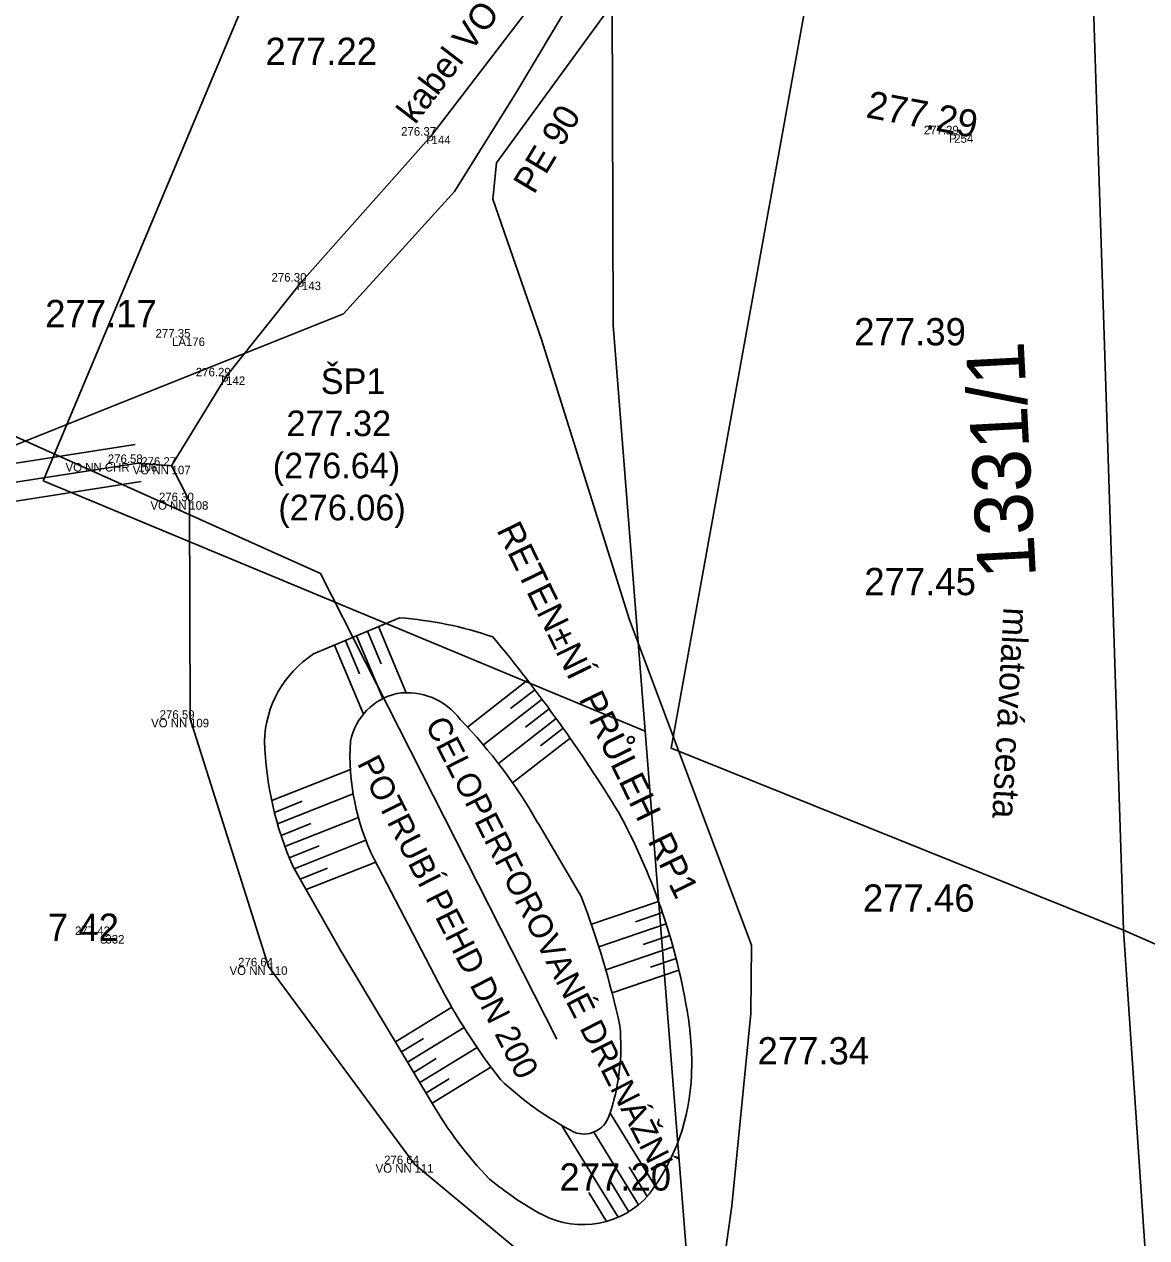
# Model space of a CAD drawing. Extents: x -601602 to -600882, y -1162594 to -1161950.
# Drawn here: x -601167.11 to -601150.66, y -1162070.19 to -1162052.4 of the extents above; entities that cross this region are included whole.
import ezdxf

# ---------------------------------------------------------------- set-up
doc = ezdxf.new("R2010")
doc.units = 0
for name, color, linetype in [('BODY', 7, 'Continuous'), ('BODY_CISLA', 7, 'Continuous'), ('BODY_KODY', 7, 'Continuous'), ('BODY_VYSKY_CELE', 7, 'Continuous'), ('G_TEXTY', 7, 'Continuous'), ('H_KOTY_VYSKOVE', 7, 'Continuous'), ('H_VYSKY_PREVZATE', 7, 'Continuous'), ('IS_CHRÁNIČKY', 7, 'Continuous'), ('IS_EON_NN', 7, 'Continuous'), ('IS_ODVODNENI_HDV', 7, 'Continuous'), ('IS_VO_AREAL', 7, 'Continuous'), ('IS_VODOVOD', 7, 'Continuous'), ('KN_Hranice parcel', 7, 'Continuous'), ('KN_Parcelní čísla', 7, 'Continuous'), ('KN_Vnitřní kresba', 7, 'Continuous')]:
    doc.layers.add(name, color=color, linetype=linetype)

# ---------------------------------------------------------------- blocks, each defined once
blk = doc.blocks.new('POINT_DISPLAY')
blk.add_line((0, 0), (0, 0))

msp = doc.modelspace()

# ---------------------------------------------------------------- linework, layer by layer
at = {"layer": 'IS_CHRÁNIČKY'}
for p, q in [((-601173.772, -1162059.848), (-601165.482, -1162058.558)), ((-601173.688, -1162060.392), (-601165.398, -1162059.102))]:
    msp.add_line(p, q, dxfattribs=at)
at = {"layer": 'IS_EON_NN'}
for points in [[(-601163.98, -1162016.16), (-601163.33, -1162016.88), (-601160.71, -1162020.48), (-601159.11, -1162022.87), (-601157.71, -1162024.95), (-601156.75, -1162026.36), (-601155.85, -1162028.35), (-601154.65, -1162035.5), (-601155.01, -1162041.12), (-601155.31, -1162044.77), (-601156.69, -1162049.18), (-601157.91, -1162051.3), (-601160.19, -1162054.43), (-601160.24, -1162054.96), (-601159.53, -1162057.02), (-601158.24, -1162061.13), (-601156.45, -1162065.9)], [(-601156.45, -1162065.9), (-601156.46, -1162066.9), (-601156.74, -1162069.72), (-601157.04, -1162071.88), (-601156.69, -1162072.3), (-601155.65, -1162072.6), (-601154.16, -1162073.09), (-601152, -1162074.34), (-601150.35, -1162074.97), (-601148.58, -1162075.26), (-601146.13, -1162075.74), (-601143.03, -1162076.23), (-601141.99, -1162076.23)]]:
    msp.add_lwpolyline(points, dxfattribs=at)
at = {"layer": 'IS_ODVODNENI_HDV'}
for p, q in [((-601162.77, -1162060.45), (-601172.63, -1162056.02)), ((-601159.303, -1162067.276), (-601162.77, -1162060.45)), ((-601162.87, -1162061.63), (-601161.61, -1162061.1)), ((-601161.917, -1162061.229), (-601161.51, -1162062.198)), ((-601162.401, -1162061.433), (-601162.196, -1162061.919)), ((-601162.24, -1162061.365), (-601161.853, -1162062.285)), ((-601162.078, -1162061.297), (-601161.878, -1162061.772)), ((-601162.562, -1162061.501), (-601162.137, -1162062.511)), ((-601159.732, -1162062.015), (-601160.614, -1162062.702)), ((-601159.521, -1162062.294), (-601160.381, -1162062.964)), ((-601159.626, -1162062.154), (-601159.982, -1162062.431)), ((-601159.417, -1162062.434), (-601159.762, -1162062.703)), ((-601159.314, -1162062.576), (-601160.161, -1162063.236)), ((-601159.212, -1162062.719), (-601159.543, -1162062.976)), ((-601159.111, -1162062.862), (-601159.953, -1162063.519)), ((-601163.483, -1162063.779), (-601162.329, -1162063.322)), ((-601163.398, -1162064.122), (-601162.288, -1162063.682)), ((-601163.443, -1162063.952), (-601163.035, -1162063.79)), ((-601163.289, -1162064.455), (-601162.212, -1162064.028)), ((-601163.346, -1162064.289), (-601162.911, -1162064.117)), ((-601158.94, -1162065.2), (-601159.58, -1162064.11)), ((-601163.226, -1162064.619), (-601162.787, -1162064.444)), ((-601163.154, -1162064.779), (-601162.102, -1162064.362)), ((-601163.17, -1162064.75), (-601162.47, -1162065.98)), ((-601163.067, -1162064.932), (-601162.663, -1162064.772)), ((-601162.979, -1162065.085), (-601161.959, -1162064.681)), ((-601161.98, -1162064.64), (-601161.04, -1162066.45)), ((-601157.813, -1162065.257), (-601158.798, -1162065.593)), ((-601157.755, -1162065.421), (-601158.149, -1162065.556)), ((-601157.701, -1162065.588), (-601158.688, -1162065.925)), ((-601157.649, -1162065.756), (-601158.04, -1162065.889)), ((-601162.47, -1162065.98), (-601161.14, -1162068.2)), ((-601157.601, -1162065.924), (-601158.587, -1162066.26)), ((-601157.556, -1162066.093), (-601157.931, -1162066.221)), ((-601157.514, -1162066.264), (-601158.495, -1162066.599)), ((-601161.67, -1162067.315), (-601160.845, -1162066.807)), ((-601161.491, -1162067.615), (-601160.664, -1162067.106)), ((-601161.58, -1162067.465), (-601161.259, -1162067.267)), ((-601161.311, -1162067.915), (-601160.472, -1162067.4)), ((-601161.401, -1162067.765), (-601161.071, -1162067.562)), ((-601161.131, -1162068.215), (-601160.27, -1162067.686)), ((-601161.221, -1162068.065), (-601160.883, -1162067.857)), ((-601157.865, -1162069.431), (-601158.523, -1162068.36)), ((-601158.406, -1162069.888), (-601159.234, -1162068.539)), ((-601158.108, -1162069.705), (-601158.761, -1162068.639)), ((-601157.978, -1162069.582), (-601158.244, -1162069.149)), ((-601158.251, -1162069.807), (-601158.539, -1162069.337)), ((-601158.574, -1162069.949), (-601158.834, -1162069.525))]:
    msp.add_line(p, q, dxfattribs=at)
for centre, radius, start, end in [((-601162.012, -1162066.56), 5.475, 71.1121, 85.7859), ((-601177.14, -1162075.423), 21.973, 31.4764, 39.7253), ((-601162.002, -1162062.961), 1.589, 123.1219, 178.1626), ((-601161.439, -1162063.095), 0.91, 103.4054, 168.2552), ((-601161.497, -1162063.164), 0.966, 36.4513, 99.0987), ((-601166.099, -1162067.811), 7.496, 29.5891, 44.1507), ((-601158.598, -1162062.738), 4.995, 181.9681, 203.7481), ((-601158.86, -1162063.108), 3.476, 176.7278, 206.1467), ((-601166.493, -1162068.374), 9.223, 9.6345, 28.6618), ((-601171.324, -1162069.912), 13.25, 12.3422, 20.8324), ((-601152.81, -1162062.178), 9.273, 207.4357, 217.8714), ((-601161.756, -1162067.632), 4.429, 357.8246, 10.4306), ((-601161.512, -1162067.378), 3.146, 340.8482, 5.4323), ((-601160.438, -1162067.684), 3.11, 323.127, 357.856), ((-601156.841, -1162064.399), 4.782, 226.5413, 242.4838), ((-601156.188, -1162065.359), 5.709, 209.8375, 224.0644), ((-601158.907, -1162068.278), 0.39, 248.3957, 340.1531), ((-601157.239, -1162065.642), 4.786, 230.3975, 241.5382), ((-601158.923, -1162068.714), 1.283, 242.2848, 319.3509)]:
    msp.add_arc(centre, radius, start, end, dxfattribs=at)
at = {"layer": 'IS_VO_AREAL'}
for points in [[(-601164.95, -1162058.87), (-601164.15, -1162057.56), (-601163.04, -1162056.17), (-601161.14, -1162054.03), (-601158.99, -1162051.22), (-601157.56, -1162048.96), (-601156.33, -1162045.65), (-601156.093, -1162044.563), (-601155.26, -1162040.45), (-601155.6, -1162034.28), (-601155.52, -1162031.87), (-601155.34, -1162029.97), (-601155.68, -1162028.1), (-601156.76, -1162025.67), (-601158.14, -1162023.37), (-601162.335, -1162016.886), (-601163.35, -1162015.61), (-601164.14, -1162013.65), (-601164.03, -1162012.35), (-601163.65, -1162011.09), (-601163.81, -1162009.97)], [(-601180.2, -1162059.82), (-601173.73, -1162060.12), (-601165.44, -1162058.83), (-601164.95, -1162058.87), (-601164.69, -1162059.39), (-601164.68, -1162062.58), (-601163.53, -1162066.21), (-601161.39, -1162069.11), (-601159.39, -1162070.77), (-601156.11, -1162072.49), (-601153.69, -1162072.64), (-601152.81, -1162073.17), (-601152.68, -1162073.88), (-601152.21, -1162076.74), (-601151.79, -1162080.24), (-601151.59, -1162080.48), (-601151.27, -1162080.62), (-601147.36, -1162080.92)]]:
    msp.add_lwpolyline(points, dxfattribs=at)
at = {"layer": 'IS_VODOVOD'}
msp.add_lwpolyline([(-601173.453, -1162076.323), (-601173.346, -1162075.998), (-601173.532, -1162075.454), (-601180.753, -1162069.349), (-601179.01, -1162062.743), (-601175.747, -1162061.656), (-601172.447, -1162060.451), (-601167.292, -1162058.586), (-601162.43, -1162056.641), (-601160.803, -1162054.849), (-601159.903, -1162053.41), (-601158.77, -1162051.508), (-601157.252, -1162048.634), (-601156.804, -1162047.317), (-601155.861, -1162044.019), (-601155.023, -1162041.098), (-601154.828, -1162039.298), (-601154.638, -1162035.819), (-601155.419, -1162031.331), (-601156.644, -1162026.466), (-601156.968, -1162024.813), (-601159.618, -1162011.435)], dxfattribs=at)
at = {"layer": 'KN_Hranice parcel'}
for p, q in [((-601151, -1162065.68), (-601152.08, -1162032.33)), ((-601149.69, -1162066.25), (-601151, -1162065.68)), ((-601149.45, -1162088.38), (-601151, -1162065.68))]:
    msp.add_line(p, q, dxfattribs=at)
for points in [[(-601158.55, -1162011.73), (-601158.56, -1162030.39), (-601158.54, -1162034.96), (-601158.53, -1162039.31), (-601158.48, -1162056.81), (-601158.01, -1162062.76), (-601156.16, -1162086.15)], [(-601152.08, -1162032.33), (-601157.63, -1162063.01), (-601151, -1162065.68)]]:
    msp.add_lwpolyline(points, dxfattribs=at)
at = {"layer": 'KN_Vnitřní kresba'}
for q in [(-601158.53, -1162039.31), (-601158.01, -1162062.76)]:
    msp.add_line((-601166.83, -1162059.09), q, dxfattribs=at)

# ---------------------------------------------------------------- block references
at = {"layer": 'BODY'}
for p in [(-601161.14, -1162054.03), (-601153.48, -1162054.01), (-601163.04, -1162056.17), (-601164.74, -1162056.99), (-601164.15, -1162057.56), (-601165.44, -1162058.83), (-601164.95, -1162058.87), (-601164.69, -1162059.39), (-601164.68, -1162062.58), (-601165.92, -1162065.75), (-601163.53, -1162066.21), (-601161.39, -1162069.11)]:
    msp.add_blockref('POINT_DISPLAY', p, dxfattribs=at)

# ---------------------------------------------------------------- texts
at = {"layer": 'BODY_CISLA'}
for s, p in [('144', (-601161.14, -1162054.155)), ('254', (-601153.48, -1162054.135)), ('143', (-601163.04, -1162056.295)), ('176', (-601164.74, -1162057.115)), ('142', (-601164.15, -1162057.685)), ('106', (-601165.44, -1162058.955)), ('107', (-601164.95, -1162058.995)), ('108', (-601164.69, -1162059.515)), ('109', (-601164.68, -1162062.705)), ('332', (-601165.92, -1162065.875)), ('110', (-601163.53, -1162066.335)), ('111', (-601161.39, -1162069.235))]:
    msp.add_text(s, height=0.125, dxfattribs=at).set_placement(p)
at = {"layer": 'BODY_KODY'}
for s, p in [('P', (-601161.216, -1162054.155)), ('P', (-601153.556, -1162054.135)), ('P', (-601163.116, -1162056.295)), ('LA', (-601164.944, -1162057.115)), ('P', (-601164.226, -1162057.685)), ('VO NN CHR', (-601166.504, -1162058.955)), ('VO NN', (-601165.52, -1162058.995)), ('VO NN', (-601165.26, -1162059.515)), ('VO NN', (-601165.25, -1162062.705)), ('S', (-601166.001, -1162065.875)), ('VO NN', (-601164.1, -1162066.335)), ('VO NN', (-601161.96, -1162069.235))]:
    msp.add_text(s, height=0.125, dxfattribs=at).set_placement(p)
at = {"layer": 'BODY_VYSKY_CELE'}
for s, p in [('276.37 ', (-601161.585, -1162054.03)), ('277.29 ', (-601153.925, -1162054.01)), ('276.30 ', (-601163.485, -1162056.17)), ('277.35 ', (-601165.185, -1162056.99)), ('276.29 ', (-601164.595, -1162057.56)), ('276.58 ', (-601165.885, -1162058.83)), ('276.27 ', (-601165.395, -1162058.87)), ('276.30 ', (-601165.135, -1162059.39)), ('276.59 ', (-601165.125, -1162062.58)), ('277.42 ', (-601166.365, -1162065.75)), ('276.64 ', (-601163.975, -1162066.21)), ('276.64 ', (-601161.835, -1162069.11))]:
    msp.add_text(s, height=0.125, dxfattribs=at).set_placement(p)
at = {"layer": 'G_TEXTY'}
msp.add_text('mlatová cesta', height=0.375, rotation=266.942, dxfattribs=at).set_placement((-601152.757, -1162060.941))
at = {"layer": 'H_KOTY_VYSKOVE'}
msp.add_text('277.29 ', height=0.4, rotation=349.1372, dxfattribs=at).set_placement((-601154.787, -1162053.759))
msp.add_text(' 7 42', height=0.4, dxfattribs=at).set_placement((-601166.911, -1162065.836))
at = {"layer": 'H_VYSKY_PREVZATE'}
for s, p in [('277.22', (-601163.575, -1162052.994)), ('277.17', (-601166.803, -1162056.839)), ('277.39', (-601154.945, -1162057.105)), ('277.45', (-601154.798, -1162060.768)), ('277.46', (-601154.818, -1162065.408)), ('277.34', (-601156.363, -1162067.648)), ('277.20', (-601159.266, -1162069.497))]:
    msp.add_text(s, height=0.4, dxfattribs=at).set_placement(p)
at = {"layer": 'IS_ODVODNENI_HDV'}
for s, p in [('ŠP1', (-601162.764, -1162057.818)), ('277.32', (-601163.267, -1162058.436)), ('(276.64)', (-601163.468, -1162059.055)), ('(276.06)', (-601163.386, -1162059.67))]:
    msp.add_text(s, height=0.375, dxfattribs=at).set_placement(p)
for s, height, rotation, p in [('RETEN±NÍ  PRŮLEH  RP1', 0.375, 295.9122, (-601160.193, -1162059.81)), ('CELOPERFOROVANÉ DRENÁŽNÍ', 0.35, 296.9265, (-601161.24, -1162062.66)), ('POTRUBÍ PEHD DN 200', 0.35, 296.9265, (-601162.237, -1162063.232))]:
    msp.add_text(s, height=height, rotation=rotation, dxfattribs=at).set_placement(p)
at = {"layer": 'IS_VO_AREAL'}
msp.add_text('kabel VO', height=0.375, rotation=52.5795, dxfattribs=at).set_placement((-601161.38, -1162053.879))
at = {"layer": 'IS_VODOVOD'}
msp.add_text('PE 90', height=0.375, rotation=59.2182, dxfattribs=at).set_placement((-601159.639, -1162054.905))
at = {"layer": 'KN_Parcelní čísla'}
msp.add_text('1331/1', height=0.85, rotation=93, dxfattribs=at).set_placement((-601152.281, -1162060.505))

doc.saveas('drawing.dxf')
